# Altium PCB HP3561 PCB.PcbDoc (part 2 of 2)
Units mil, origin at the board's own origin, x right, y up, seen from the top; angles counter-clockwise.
Board outline 2229 x 3254 mil, 4 copper layers (Component Side, Signal Layer 2, Signal Layer 1, Solder Side), stack 33.234 mil thick; 84 components, 95 nets, 407 pads, 246 vias.
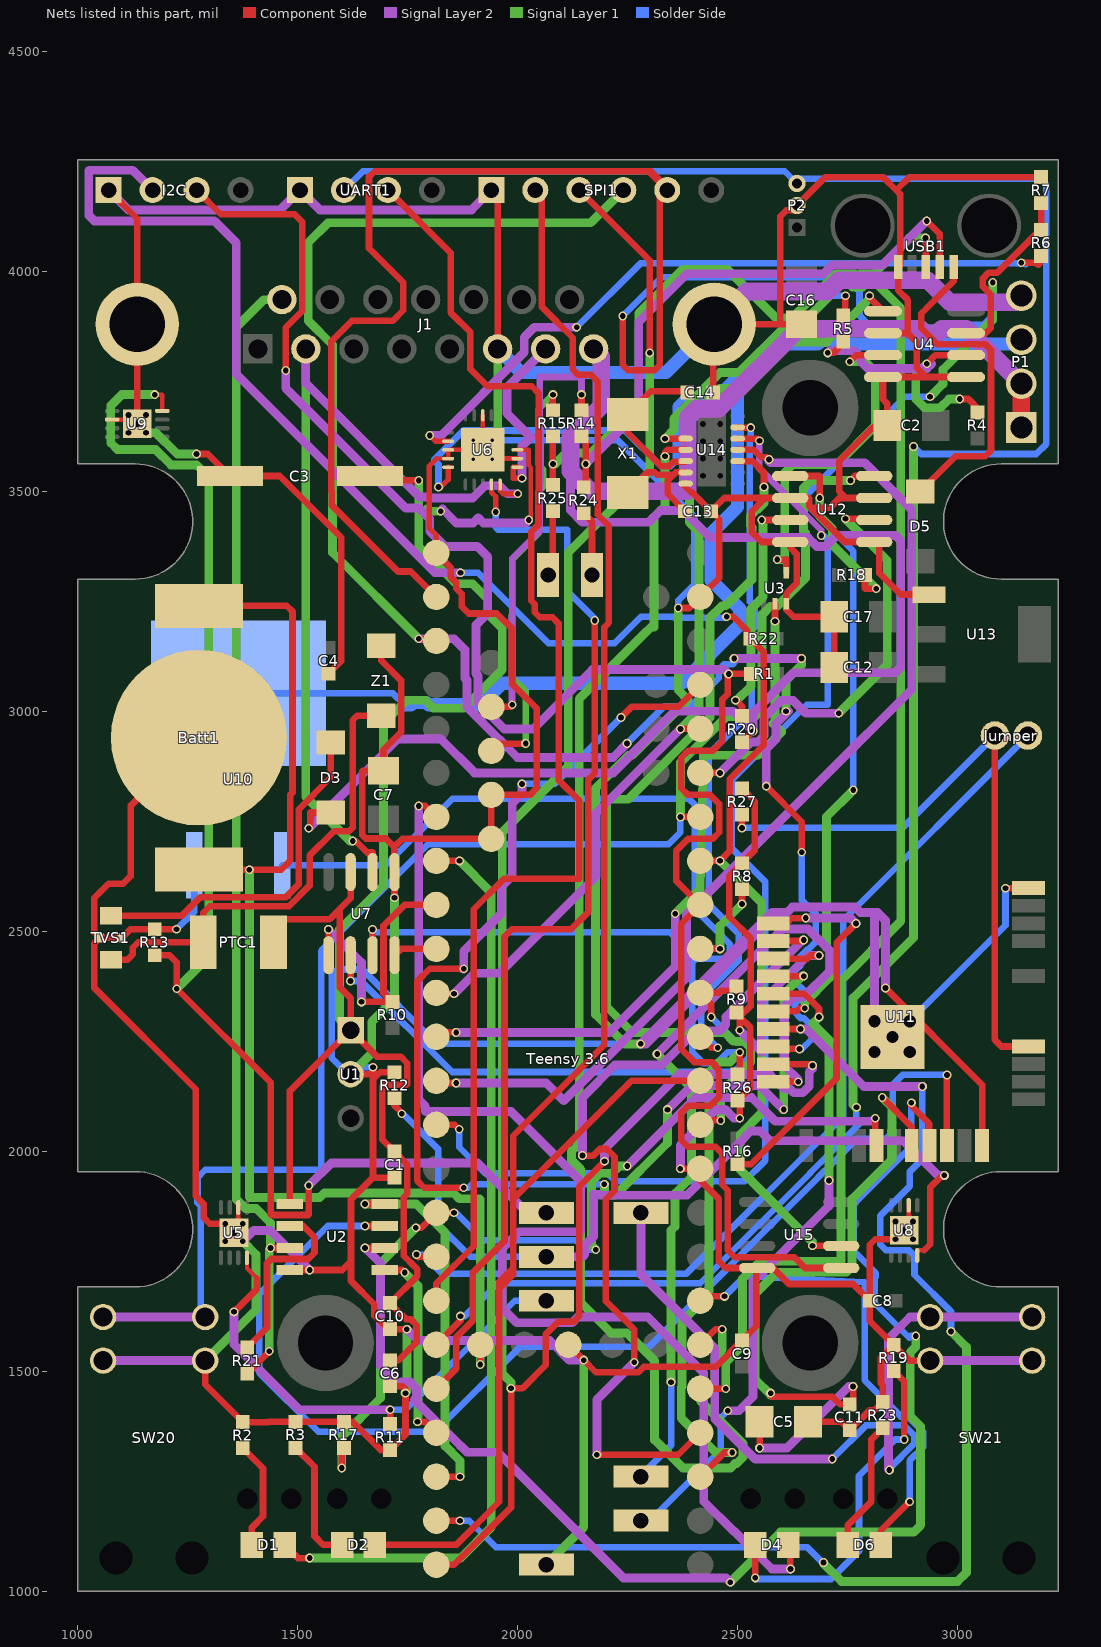
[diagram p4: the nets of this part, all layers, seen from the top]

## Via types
v1: diameter 20, hole 13, Component Side to Solder Side, 238 vias
v2: diameter 19.68, hole 7.87, Component Side to Solder Side, 4 vias
v3: diameter 50, hole 28, Component Side to Solder Side, 4 vias

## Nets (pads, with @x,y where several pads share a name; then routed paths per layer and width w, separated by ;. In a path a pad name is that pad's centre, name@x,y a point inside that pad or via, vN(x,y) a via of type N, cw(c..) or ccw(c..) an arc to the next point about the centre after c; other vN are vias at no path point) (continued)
GND: "Teensy 3.6.14" "Teensy 3.6.17" "Teensy 3.6.32" "Teensy 3.6.59" "Teensy 3.6.78" "Teensy 3.6.79" "Teensy 3.6.90" Batt1.2 C1.1 C2.1 C3.2 C4.2 C5.1 C6.1 C7.2 C8.1 C9.1 C10.2 C11.1 C12.1 C13.1 C14.1 C16.1 C17.1 I2C.1 J1.6 J1.16 J1.17 P1.4 P2.2 R2.2 R3.2 R7.2 R8.2 R9.2 R11.2 R12.2 R13.2 R17.2 R19.2 R23.2 R26.2 R27.1 SPI1.1 SW20.2 SW20.4 SW21.2 SW21.4 TVS1.3 U1.2 U2.8 U3.3 U4.2 U4.4 U4.5 U5.0 U5.2 U6.3 U6.4 U6.12 U6.18 U6.21 U7.5 U8.0 U8.2 U9.0 U9.2 U10.3 U11.9 U11.12 U11.28 U11.29 U12.2 U12.4 U12.5 U12.7 U13.1 U14.7 U15.4 UART1.1 USB1.4 Z1.1 | length 26968.1
  Component Side w10: U9.2@1077.91,3663.31 1115,3663.31 U9.0@1121.89,3663.31 ; U5.0@1364.84,1845.16 U5.2@1364.84,1872.09 ; 1816,3574.72 U6.4@1841.89,3574.72 U6.3@1841.89,3594.41 U6.21@1920.63,3594.41 U6.18@1920.63,3673.15 ; U8.0@2888.73,1850.16 U8.2@2888.73,1877.09
  Component Side w11.81: 1815,3360 1815,3400.44 1799.09,3416.34 1799.09,3557.82 1816,3574.72 ; U6.21@1944.25,3574.72 U6.12@1999.37,3574.72
  Component Side w14.76: U5.0@1364.84,1845.16 v1(1375,1835) ; U8.0@2888.73,1850.16 v1(2898.89,1840)
  Component Side w15: I2C.1@1070,4185 1135,4120 J1.16@1135,3880 U9.0@1135,3653.47 1144.53,3663 1155,3663 v1(1155,3673.47) ; v1(1115,3633.47) 1115,3663.31 v1(1115,3673.47) ; v1(1224.53,2504.53) R13.2@1175,2504.53 1119.53,2504.53 TVS1.3@1100,2485 TVS1.3@1050,2485 ; v1(1270,3585) 1295.55,3585 C3.2@1345.55,3535 1459,3535 1599,3395 1599,3114.47 C4.2@1570,3085.47 ; Batt1.2@1275,2940 1120,2785 1120,2625 1103,2608 1070,2608 1037,2575 1037,2498 TVS1.3@1050,2485 ; SW20.4@1289.5,1524 1289.5,1469.55 R2.2@1375,1384.05 1434,1384.05 1434.47,1384.53 R3.2@1495,1384.53 R17.2@1605,1384.53 1624.92,1384.53 1688.98,1320.47 R11.2@1710,1320.47 1745,1355.47 v1(1745,1450) 1745,1458.41 1737.94,1465.47 C6.1@1710,1465.47 ; v1(1335,1795) v1(1335,1835) 1300,1835 1286,1849 1286,1880 1268,1898 1268,2141 1037,2372 1037,2472 TVS1.3@1050,2485 ; U5.0@1355,1815 1365,1825 U5.0@1375,1825 ; v1(1375,1795) U5.0@1375,1825 ; v1(1375,1835) U5.0@1375,1825 ; U2.8@1482.13,1730 v1(1527,1730) 1601,1730 1621,1750 ; U1.2@1620,2175 1671,2175 ; v1(1671,2191) 1671,2175 ; Z1.1@1690,3149 1690,3115 1735,3070 1735,2952.5 1695,2912.5 C7.2@1695,2865.12 1648,2865.12 1647,2864.12 1647,2718.28 1654.39,2710.89 1700,2710.89 1720,2690.88 ; C10.2@1710,1595.47 1747.53,1595.47 v1(1748,1595) 1705,1595 1674,1626 1674,1652 1621,1705 1621,1750 ; C1.1@1720,1940 1671.75,1940 ; R12.2@1720,2179.53 1687.5,2179.53 1682.97,2175 ; v1(1720,2576) U7.5@1720,2634.49 1720,2690.88 ; 1815,3360 1847.5,3327.5 1847.5,3305.68 1860,3293.18 1860,3280 1872.56,3267.44 1872.56,3238.7 1888.76,3222.5 1952.5,3222.5 1987,3188 1987,3061.25 1988.75,3061.25 2043,3007 2043,2825 2028,2810 1940,2810 1940,2710 1737.5,2710 1720,2692.5 1720,2690.88 ; U6.21@1920.63,3594.41 1931.22,3605 1942.28,3605 v2(1942.28,3616.06) ; SPI1.1@1940,4185 1954.49,4170.51 J1.6@1954.49,3824.09 ; v2(1942.28,3572.76) U6.21@1944.25,3574.72 ; 2115,1560 v1(2150,1525) 2177.5,1497.5 2274.32,1497.5 2286.82,1510 2450.47,1510 C9.1@2510,1569.53 2542.5,1602.03 2542.5,1732.5 U15.4@2544.53,1734.53 ; v1(2365,3235) 2390,3235 2415,3260 2458,3303 2458,3436.53 C13.1@2439.53,3455 ; v1(2369.84,1960) 2415,1960 2415,1933.5 2457.5,1891 2457.5,1750 2472.97,1734.53 U15.4@2544.53,1734.53 ; U14.7@2381.89,3517.64 2381,3517.64 2381,3510.5 2393.5,3498 2396.53,3498 C13.1@2439.53,3455 ; C14.1@2444.53,3725 2444.53,3801 2446.81,3803.29 J1.17@2446.81,3880 2545,3880 2545.12,3879.88 2598,3879.88 ; v1(2505,2075) 2505,2110 R26.2@2500,2115 2529,2144 2529,2281.47 R9.2@2505,2305.47 ; v1(2505,2275) R9.2@2505,2305.47 ; R27.1@2510,2824.53 2539,2795.53 2539,2683.53 R8.2@2510,2654.53 2481,2625.53 2481,2533 2529.47,2484.53 2529.47,2329.94 R9.2@2505,2305.47 ; U11.12@2581.04,2437.79 2657.79,2437.79 2665,2445 v1(2685,2445) ; C16.1@2645,3879.88 2598,3879.88 ; C5.1@2660.12,1385 2735.47,1385 C11.1@2755,1365.47 2801,1411.47 2811.95,1411.47 R23.2@2830,1429.53 2830,1468 2826,1472 2826,1530.53 R19.2@2855,1559.53 ; C12.1@2719.88,3100 C17.1@2719.88,3215 2627.09,3215 2610.59,3231.5 U3.3@2610.59,3244.57 2610.59,3268 2634,3291.41 2634,3357.82 2619.53,3372.29 U12.4@2619.53,3385 2555,3385 2532.5,3407.5 2532.5,3455 2562.5,3485 ; U12.7@2810.47,3485 2746,3485 ; U4.2@2830.51,3860 2886,3860 ; v1(2836,2370.84) 3055.84,2151 U11.28@3055.84,2012.91 ; v1(2858.89,1800) 2812.97,1800 2800.47,1787.5 C8.1@2800.47,1660 ; v1(2898.89,1800) v1(2898.89,1840) ; U13.1@2934.84,3265.55 2871,3265.55 2822,3314.55 2822,3385 U12.5@2810.47,3385 2744,3385 2666.5,3462.5 ; SW21.2@2937.5,1524 2890.53,1524 R19.2@2855,1559.53 ; U4.5@3019.49,3760 2928.18,3760 ; v1(3109,2598) U11.9@3160.96,2598.03 ; R7.2@3190,4214.53 2890.53,4214.53 2860.5,4184.5 ; 1621,1750 1621,1890 1671,1940 ; 1671,1940 1671.75,1940 ; 1671,1940 1671,2175 ; 1671,2175 1682.97,2175 ; 1671.75,1940 1671.75,2163.78 1682.97,2175 ; C13.1@2439.53,3455 2469.53,3485 2562.5,3485 ; U15.4@2544.53,1734.53 2580.47,1734.53 2617,1698 2762.47,1698 C8.1@2800.47,1660 ; 2562.5,3485 U12.2@2619.53,3485 2662,3485 2663,3484 2663,3466 2666.5,3462.5 ; 2598,3879.88 2597,3880.88 2597,4125 2611,4139 2635,4139 P2.2@2635,4150 2699.53,4214.53 2830.47,4214.53 2860.5,4184.5 ; 2666.5,3462.5 2709,3462.5 2731.5,3485 2746,3485 ; 2746,3485 2731,3500 2731,3569 2808,3646 2839.88,3646 C2.1@2839.88,3650 2839.88,3700 2830.51,3709.37 U4.4@2830.51,3760 2928.18,3760 ; C8.1@2800.47,1660 2800.47,1614.05 R19.2@2855,1559.53 ; 2860.5,4184.5 2870,4175 2870,4015 USB1.4@2865,4010 2865,3957 2887,3935 2887,3861 2886,3860 ; 2886,3860 2907.5,3838.5 2907.5,3780.68 2928.18,3760
  Signal Layer 2 w20: SW20.2@1057.5,1524 SW20.4@1289.5,1524 ; I2C.1@1070,4185 1115,4140 1460,4140 UART1.1@1505,4185 1550,4140 1895,4140 SPI1.1@1940,4185 ; v1(1375,1795) 1400,1820 1437,1820 v1(1527,1730) ; v1(1748,1595) 1773.47,1569.53 2072.47,1569.53 2117,1525 v1(2150,1525) ; v2(1898.98,3572.76) v2(1942.28,3572.76) ; v2(1898.98,3616.06) v2(1942.28,3616.06) ; v1(2369.84,1960) 2369.84,2013.67 2451.17,2095 2471.88,2095 2491.88,2075 v1(2505,2075) ; v1(2505,2275) 2554.29,2225.71 2554.29,2339.29 2660,2445 v1(2685,2445) ; 2589,2543 2578.5,2543 v1(2279.5,2244) 2292,2244 2591,2543 2612.64,2543 2624.64,2555 2767.15,2555 2779.15,2543 2811,2543 ; v3(2811,2225.47) 2817.61,2225.47 U11.29@2851.91,2259.76 ; v3(2811,2295.47) 2811,2543 ; v1(2836,2370.84) 2836,2525 2818,2543 2811,2543 ; v1(2858.89,1800) v1(2898.89,1800) ; U8.0@2878.89,1820 2868.89,1830 2858.89,1830 v1(2858.89,1840) v1(2898.89,1840) ; SW21.2@2937.5,1524 SW21.4@3169.5,1524
  Signal Layer 2 w40: J1.17@2446.81,3880 2521.3,3954.49 2704.99,3954.49 2730.5,3980 2932,3980 2982,3930 3130,3930 P1.4@3145,3945
  Signal Layer 1 w20: v1(1155,3673.47) v1(1155,3633.47) 1177.53,3633.47 1226,3585 v1(1270,3585) ; SW20.4@1289.5,1524 1405,1639.5 1405,1765 v1(1375,1795) ; U1.2@1620,2175 1668,2223 1668,2294 1720,2346 v1(1720,2576) ; v1(1745,1450) 1743.5,1450 1748,1454.5 v1(1748,1595) ; v2(1942.28,3572.76) v2(1942.28,3616.06) 1954.49,3628.27 J1.6@1954.49,3824.09 ; 2065,1060 2150,1145 v1(2150,1525) ; v1(2279.5,2244) 2244,2244 2177,2311 2177,2825 2252,2900 2260.36,2900 2387,3026.64 2365,3048.64 v1(2365,3235) ; v3(2811,2225.47) v3(2811,2295.47) ; v3(2891,2225.47) v3(2891,2295.47)
  Solder Side w15: v1(1115,3633.47) v1(1155,3633.47) ; v1(1224.53,2504.53) 1265,2545 U10.3@1265,2649.84 ; v1(1335,1795) v1(1375,1795) ; v1(1671,2191) 1598.5,2191 1577,2212.5 1577,2400 1590,2413 1647,2413 1816,2244 v1(2279.5,2244) ; v2(1898.98,3616.06) v2(1942.28,3616.06) 2227.94,3616.06 2401,3443 2401,3288 2365,3252 v1(2365,3235) ; v3(2811,2225.47) v3(2891,2225.47) ; v3(2891,2295.47) 3109,2513.47 v1(3109,2598)
  Solder Side w30: J1.6@1954.49,3824.09 2008.58,3770 2336.81,3770 J1.17@2446.81,3880
"GPS RX": "Teensy 3.6.41" P2.3 UART1.2 | length 5337
  Component Side w15: 1815,1560 1870,1615 v1(1870,1625)
  Signal Layer 1 w20: v1(2770,2100) 2770,2097.84 2762.16,2105.67 2762.16,2348 2900,2485.84 v1(2900,3602)
  Solder Side w15: UART1.2@1605,4185 1648,4228 2607,4228 P2.3@2635,4200 2635,4211 3187.5,4211 3202,4196.5 3202,3608 3179,3585 2917,3585 v1(2900,3602) ; v1(1870,1625) 1880,1625 1955,1700 2415,1700 2665,1950 2665,1951.1 2689.9,1976 2691,1976 2780,2065 2770,2075 v1(2770,2100)
"GPS TX": "Teensy 3.6.40" UART1.3 | length 3029.2
  Component Side w15: UART1.3@1705,4185 1847.5,4042.5 1847.5,3907 1892,3862.5 1892,3778 1931,3739 2032,3739 2047.5,3723.5 2047.5,3424.5 2031,3408 2031,3251.28 2038.61,3243.68 2038.61,3225.39 2050,3214 2079,3214 2093,3200 2093,2844 2140,2797 2140,2620 2139,2619 1969,2619 1899.97,2549.97 1899.97,1783.97 1815,1699 1815,1660
"Hst USB_N": "Teensy 3.6.76" R14.1 | length 1000.3
  Component Side w15: 1940,3010 1954,2996 1968,3010 v1@1985,3010 ; R14.1@2145,3684.53 v1(2145,3720)
  Signal Layer 2 w15: v1(1987.5,3015) 1987.14,3015.36 1987.14,3216.89 1987.5,3217.24 1987.5,3347.5 2050,3410 2050,3518.18 2052.5,3520.68 2052.5,3632.79 2050,3635.29 2050,3760 2145,3760 v1(2145,3720)
"Hst USB_P": "Teensy 3.6.77" R15.1 | length 973.2
  Component Side w15: 1940,2910 1956.68,2926.68 v1(2018,2926.68) ; R15.1@2080,3684.53 v1(2080,3720)
  Signal Layer 1 w15: v1(2018,2926.68) 2018,3046 1987.5,3076.5 1987.5,3197.89 1987.14,3198.25 1987.14,3216.89 1987.5,3217.24 1987.5,3345 2047.5,3405 2047.5,3500.32 2057.5,3510.32 2057.5,3549.68 2047.5,3559.68 2047.5,3687.5 v1(2080,3720)
"J1708 RX": "Teensy 3.6.4" "Teensy 3.6.29" U4.1 | length 2243.6
  Component Side w15: 1815,2360 1817.21,2357.79 v1(1855,2357.79) ; v1(2370,2960) 2415,2960 ; v1(2800,3945) 2800,3940.51 U4.1@2830.51,3910
  Signal Layer 2 w20: v1(1855,2357.79) 1855.62,2357.79 1902.47,2404.64 1957.64,2404.64 2178,2625 2178,2768 v1(2370,2960)
  Signal Layer 1 w20: v1(2370,2960) 2412,3002 2412,3408.25 2390.25,3430 2390.25,3665.25 2459.65,3734.65 2506.3,3734.65 2611.65,3840 2702,3840 2800.51,3938.51 2800,3939.02 v1(2800,3945)
"J1708 TX": "Teensy 3.6.3" U3.2 | length 1614.3
  Component Side w15: 1815,2260 1825,2270 v1(1860,2270) ; v1(2585,3205) U3.2@2585,3244.57
  Signal Layer 2 w20: v1(1860,2270) 2208,2270 2358,2420 v1(2358,2540)
  Signal Layer 1 w20: v1(2358,2540) 2415,2597 2422,2900 2547,2900 2600,2953 2580.64,2972.36 2585,2976.72 v1(2585,3205)
J1708+: R5.2 U6.5 | length 1400.7
  Component Side w11.81: v1(1820,3510) 1825.47,3510 1825.97,3510.5 1841.89,3526.42 U6.5@1841.89,3555.04
  Component Side w15: R5.2@2740,3899.53 2745,3904.53 v1(2745,3945)
  Solder Side w15: v1(1820,3510) 1820,3561.41 1810,3571.41 1877,3638.41 2244.09,3638.41 2325,3557.5 2348,3557.5 2359,3568.5 2359,3694 2375,3710 2440,3710 2675,3945 v1(2745,3945)
J1708-: R6.2 U6.2 | length 1669
  Component Side w11.81: v1@1800,3624.91 v1(1800,3626.94) 1812.84,3614.09 U6.2@1841.89,3614.09
  Component Side w15: v1(3145,4020) 3178,4020 3183,4015 3190,4022 R6.2@3190,4035.47
  Signal Layer 2 w20: v1(1800,3626.94) 1825.59,3626.94 2015,3816.34 2015,3850.5 2037.5,3873 v1(2134,3873)
  Solder Side w15: v1(2134,3873) 2280,4019 v1@3152,4019 ; v1(3145,4020) 3151,4020 v1@3152,4019 ; v1@3152,4019 3158,4019 3155,4016 v1@3152,4019
LIN: J1.2 U6.10 U7.6 | length 2010.9
  Component Side w11.81: U6.10@1960,3515.67 1960,3501.5 1967.03,3494.47 v1(2000,3494.47)
  Component Side w15: v1(1625,2705) 1631.99,2705 1657.99,2679 1670,2679 U7.6@1670,2634.49
  Signal Layer 2 w20: J1.2@1518.27,3824.09 1518.27,3746.38 1777.64,3487 1797.64,3487 1799.64,3485 1898,3485 1925.68,3512.68 1958.32,3512.68 1976.53,3494.47 v1(2000,3494.47)
  Signal Layer 1 w20: J1.2@1518.27,3824.09 1518.27,2805.73 1619,2705 v1(1625,2705)
"LIN1 RX": "Teensy 3.6.6" R10.1 U7.1 | length 645
  Component Side w15: U7.1@1570,2445.51 v1(1570,2504) ; v1(1645,2339.53) R10.1@1715,2339.53 1695,2359.53 1695,2512.5 1742.5,2560 1815,2560
  Signal Layer 2 w20: v1(1570,2504) 1645,2429 v1(1645,2339.53)
"LIN1 TX": "Teensy 3.6.5" U7.4 | length 101
  Component Side w15: U7.4@1720,2445.51 1734.49,2460 1815,2460
"LIN !WAKE": "Teensy 3.6.24" R8.1 U7.3 | length 1112.9
  Component Side w15: U7.3@1670,2445.51 v1(1670,2504) ; v1(2510,2562) R8.1@2510,2595.47 ; 2415,2460 v1(2460,2460) 2415,2460
  Signal Layer 1 w20: v1(2460,2460) 2460,2512 v1(2510,2562)
  Solder Side w15: v1(1670,2504) 1676.5,2497.5 2347.68,2497.5 2385.18,2460 v1(2460,2460)
"LIN CS": "Teensy 3.6.23" R9.1 U7.2 | length 1359.2
  Component Side w15: v1(1620,2387) U7.2@1620,2445.51 ; v1(2440,2305) 2440,2335 2415,2360 2457,2360 2461.53,2364.53 R9.1@2505,2364.53
  Solder Side w15: v1(1620,2387) 1644,2387 1851,2180 2491.82,2180 2527.5,2215.68 2527.5,2234.32 2514.32,2247.5 2497.5,2247.5 v1(2440,2305)
"LIN Switch": "Teensy 3.6.42" U6.9 | length 2472.6
  Component Side w11.81: U6.9@1940.32,3515.67 1940.32,3497.41 1950,3487.73 v1(1950,3453)
  Component Side w15: 1815,1460 1860,1505 1860,1576.72 1897.5,1614.22 1897.5,1723 1970,1795.5 1970,2487.5 1987,2504.5 2121.5,2504.5 2160,2543 2160,2844 2175,2859 v1(2175,3206.53)
  Solder Side w15: v1(1950,3453) 1950,3418.28 1955.78,3412.5 2112.5,3412.5 2112.5,3273.82 2175,3211.32 v1(2175,3206.53)
NetBatt1_1: "Teensy 3.6.15" Batt1.1 | length 2703.2
  Component Side w15: Batt1.1@1275,2640 v1(1390,2640) 1462.5,2640 1482.5,2660 1482.5,2809.85 1488,2815.35 1488,3227 1475,3240 Batt1.1@1275,3240 ; v1(1915,1515) 1915,1560
  Signal Layer 1 w20: v1(1390,2640) 1390,1896 1391,1895 1550,1895 1560,1905 1854.12,1905 1867.12,1892 1913,1892 1915,1890 v1(1915,1515)
NetC5_2: C5.2 C11.2 U11.24 | length 1628.6
  Component Side w15: C5.2@2549.88,1385 2550,1384.88 v1(2550,1325.47) ; v1(2575,1450) 2575,1445 2578.5,1441.5 2716.03,1441.5 2733,1424.53 C11.2@2755,1424.53 2762.47,1432 v1(2762.47,1465) ; v1(2829,2122) 2895.84,2055.16 U11.24@2895.84,2012.91
  Signal Layer 2 w20: v1(2550,1325.47) 2612.97,1325.47 2752.5,1465 v1(2762.47,1465)
  Signal Layer 1 w20: v1(2575,1450) 2575,1446 2540,1481 2540,1675.5 2589.5,1725 2747.5,1725 2760,1737.5 2760,1891 2851,1982 2851,2100 v1(2829,2122)
NetC13_2: C13.2 U14.6 X1.1 | length 267.6
  Component Side w15: X1.1@2250,3497.83 2295.4,3543.23 2311.67,3543.23 2317.4,3537.5 2353.5,3537.5 2359.23,3543.23 ; C13.2@2380.47,3455 2341,3494.47 2341,3525 2359.23,3543.23 ; U14.6@2381.89,3543.23 2359.23,3543.23
NetC14_2: C14.2 U14.5 X1.2 | length 368
  Component Side w15: U14.5@2381.89,3568.82 2380.57,3567.5 2354.32,3567.5 2344.32,3557.5 2325.68,3557.5 2250,3633.18 X1.2@2250,3675 2302.5,3727.5 2382.97,3727.5 C14.2@2385.47,3725
NetD1_1: "Teensy 3.6.7" D1.1 | length 2108.8
  Component Side w15: D1.1@1470.4,1105 1500.4,1075 v1(1527,1075) ; 1815,2660 v1(1867.88,2660)
  Signal Layer 1 w20: v1(1527,1075) 1870,1075 1940,1145 1940,2587.88 v1(1867.88,2660)
NetD1_2: D1.2 R2.1 | length 249.6
  Component Side w15: R2.1@1375,1325 1421,1279 1421,1170 1395.6,1144.6 D1.2@1395.6,1105
NetD2_1: "Teensy 3.6.21" D2.1 SPI1.2 | length 4092.5
  Component Side w15: D2.1@1675.4,1105 1860,1105 1958,1203 1958,1687 ; SPI1.2@2040,4185 2055,4170 2055,3919.5 2125,3849.5 2125,3777.5 2137.5,3765 2167,3765 2182,3750 2182,3447 2207,3422 2207,3201 2197,3191 2197,2242 1990,2035 1990,1891 ; 2415,2160 2259,2160 1990,1891 ; 1958,1687 1958,1703 1990,1735 ; 1958,1687 1990,1719 1990,1735 ; 1990,1735 1990,1891
NetD2_2: D2.2 R3.1 | length 289.2
  Component Side w15: R3.1@1495,1325.47 1538,1282.47 1538,1125 1558,1105 D2.2@1600.6,1105
NetD3_2: D3.2 TVS1.1 | length 809.1
  Component Side w15: TVS1.1@1075,2535 1236,2535 1278,2577 1472,2577 1502.5,2607.5 1502.5,2777.5 1575,2850 D3.2@1575,2929
NetD4_1: "Teensy 3.6.8" D4.1 | length 2753
  Component Side w15: v1(1775,2785) 1790,2785 1815,2760 ; D4.1@2615.4,1105 2620,1100.4 v1(2620,1050)
  Signal Layer 2 w20: v1(1775,2785) 1775,2117.09 1790,2102.09 1790,2091 1791,2090 1985,2090 2143,1932 2143,1818 2142,1817 2003,1817 1965,1779 1965,1643 1998,1610 2123.71,1610 2136.71,1623 2295.71,1623 2423,1495.71 2423,1203.64 2489.83,1136.82 2491.18,1136.82 2578,1050 v1(2620,1050)
NetD4_2: D4.2 R19.1 | length 812.4
  Component Side w15: v1(2540.12,1030) 2540.12,1104.52 D4.2@2540.6,1105 ; R19.1@2855,1500.47 2878.89,1476.58 v1(2878.89,1344.47)
  Solder Side w15: v1(2540.12,1030) 2542.62,1027.5 2712.5,1027.5 2776,1091 2776,1262 2858.47,1344.47 v1(2878.89,1344.47)
NetD5_1: D5.1 USB1.1 | length 776.3
  Component Side w15: D5.1@2915,3500 2995,3580 3063,3580 3076,3593 3076,3821.5 3062.5,3835 2953.8,3835 2917.5,3871.3 2917.5,3904.32 2927.5,3914.32 2927.5,3914.5 2990.98,3977.98 USB1.1@2990.98,4010
NetD6_1: "Teensy 3.6.51" D6.1 | length 1098.2
  Component Side w15: 2415,1660 2425,1670 v1(2470,1670) ; D6.1@2825.4,1105 2825.4,1137.5 v1(2891,1203.1)
  Solder Side w15: v1(2470,1670) 2516,1716 2789,1702 2789,1479 2871.5,1396.5 2886.97,1396.5 2921.39,1362.08 2921.39,1326.87 2891,1296.48 v1(2891,1203.1)
NetD6_2: D6.2 R23.1 | length 298.4
  Component Side w15: D6.2@2750.6,1105 2750.6,1150 2804,1203.4 2804,1344.47 R23.1@2830,1370.47
NetI2C_2: "Teensy 3.6.26" I2C.2 R22.2 U15.6 | length 4073
  Component Side w15: 2415,2660 v1(2460,2660) 2481.75,2681.75 2481.75,2845.45 2559,2922.7 2559,3135.47 R22.2@2529.47,3165 2521.49,3172.99 2521.49,3183.99 2490.47,3215 v1(2475,3215) ; v1(2670,1785) 2735,1785 U15.6@2735.47,1784.53
  Signal Layer 2 w20: I2C.2@1170,4185 1125,4230 1026,4230 1025,4229 1025,4127.5 1037.5,4115 1310,4115 1360,4065 1360,3767 1812,3315 v1(1870,3315)
  Signal Layer 1 w20: v1(2460,2660) 2555,2565 2555,2087 2506,2038 2506,1957.53 2670,1793.53 v1(2670,1785)
  Solder Side w15: v1(1870,3315) 1910,3315 2070,3155 2220,3155 2280,3215 2353.18,3215 2355.68,3212.5 2472.5,3212.5 v1(2475,3215)
NetI2C_3: "Teensy 3.6.25" I2C.3 R1.2 U15.5 | length 4395.1
  Component Side w15: I2C.3@1270,4185 1325,4130 1492.5,4130 1510,4112.5 1510,3910 1472.5,3872.5 v1(1472.5,3775) ; R1.2@2530.47,3085 v1(2479.53,3085) 2477.5,3085 2477.5,3039.32 2465,3026.82 2465,2932 2443,2910 2387.5,2910 2372,2894.5 2372,2825 2387,2810 2437.5,2810 2458,2789.5 2458,2725 2443,2710 2387.5,2710 2360,2682.5 2360,2615 2415,2560 2372,2517 2372,2232.5 2402,2202.5 2442.5,2202.5 2448.5,2196.5 2448.5,2193.68 2457.5,2184.68 2457.5,2147 2458,2146.5 2458,2123.5 2437.5,2103 2387.5,2103 2372,2087.5 2372,2025 2387,2010 2450,2010 2465,1995 2465,1923.74 2477.5,1911.24 2477.5,1775 2493.5,1759 2629,1759 2653.47,1734.53 U15.5@2735.47,1734.53
  Signal Layer 2 w20: v1(1472.5,3775) 1472.5,3734.88 1745.38,3462 1776,3462 1800,3438 1800,3409.64 1834.64,3375 1908,3375 1931.94,3351.06 1931.94,3222.94 1905,3196 1905,3085.71 1910,3080.71 1910,3019.64 1970,2959.64 2034.64,2959.64 2170,3095 2469.53,3095 v1(2479.53,3085)
NetJumper_1: "Teensy 3.6.39" Jumper.1 | length 2226
  Component Side w15: v1(1770,1765) 1770,1763 1774,1759 1775,1760 1815,1760
  Solder Side w15: v1(1770,1765) 1785,1765 1829,1721 2382.82,1721 2740,2078.18 2740,2525 Jumper.1@3160,2945
NetJumper_2: Jumper.2 R27.2 U11.4 | length 1466.6
  Component Side w15: v1(2510,2735) R27.2@2510,2765.47 ; Jumper.2@3085,2945 3085,2253.03 3100,2238.03 U11.4@3160.96,2238.03
  Solder Side w15: v1(2510,2735) 2875,2735 Jumper.2@3085,2945
NetP1_3: P1.3 U10.2 | length 2513.4
  Solder Side w15: U10.2@1365,3041.57 1715.43,3041.57 1742,3015
  Solder Side w30: 1742,3015 1757.57,3015 1762.57,3020 1792.43,3020 1797.43,3015 1915.78,3015 1964.78,3064 2372.68,3064 2505,3196.32 2505,3233 2440,3298 2440,3405 2500,3465 2500,3594.17 2499.88,3594.29 2499.88,3635.71 2500,3635.83 2500,3724.36 2610.64,3835 2682.57,3835 2692.57,3845 2717.43,3845 2727.43,3835 3135,3835 P1.3@3145,3845
NetPTC1_1: PTC1.1 TVS1.2 Z1.2 | length 1075.9
  Component Side w15: TVS1.2@1075,2435 1112.5,2435 1125,2447.5 1125,2462.5 1137.5,2475 PTC1.1@1285,2475 1285,2542 1300,2557 1480.28,2557 1527,2603.72 1527,2672 1582.5,2727.5 1616.5,2727.5 1625,2736 1625,2980 1635,2990 Z1.2@1690,2990
NetR4_2: R4.2 R5.1 U4.6 | length 691.5
  Component Side w15: v1(2705,3815) 2718,3815 2740,3837 R5.1@2740,3840.47 ; v1(2930,3790) 2950,3810 U4.6@3019.49,3810 ; v1(3005,3710) 3024.53,3710 3050,3684.53 R4.2@3045,3679.53
  Signal Layer 2 w20: v1(2705,3815) 2710,3820 2765.36,3820 2780,3805.36 2780,3795.36 2796.07,3779.28 2930.46,3779.28 2941.18,3790 v1(2930,3790)
  Signal Layer 1 w20: v1(2930,3790) 2905,3765 2905,3710 2925,3690 2960.86,3690 2980.86,3710 v1(3005,3710)
NetR6_1: R6.1 R7.1 U4.7 | length 420
  Component Side w15: U4.7@3019.49,3860 3064,3860 3075.3,3871.3 3075.3,3947.89 3057.5,3965.68 3057.5,3984.32 3070.68,3997.5 3090.68,3997.5 3187.71,4094.53 R6.1@3190,4094.53 R7.1@3190,4155.47
NetR11_1: "Teensy 3.6.54" R11.1 U5.8 | length 1134.7
  Component Side w10: U5.8@1384.53,1757.91 1384.53,1734.11 1407.03,1711.61
  Component Side w15: v1(1355,1634.76) 1407.03,1686.79 1407.03,1711.61 ; R11.1@1710,1379.53 v1(1710,1412)
  Signal Layer 2 w20: v1(1355,1634.76) 1355,1561 1504,1412 v1(1710,1412)
  Solder Side w15: v1(1710,1412) 1745.18,1412 1993.18,1660 2065,1660
NetR12_1: "Teensy 3.6.53" R12.1 U8.8 | length 1961.4
  Component Side w10: U8.8@2908.42,1762.91 2908.42,1775 2924.5,1775
  Component Side w14.76: 2924.5,1775 2937,1787.5
  Component Side w15: R12.1@1720,2120.47 1720,2104 1736.38,2087.62 v1(1736.38,2085) ; 2937,1787.5 2937.5,1788 2937.5,1917.5 2965,1945 v1(2970,1945)
  Signal Layer 2 w20: 2065,1760 2147.5,1760 2152.5,1765 2152.5,1786.36 2172,1805.86 2172,1901.5 2185.14,1901.5 2186.64,1900 2385,1900 2515.6,2030.6 2515.6,2031.36 2530.24,2046 2550.95,2046 2573.43,2023.53 2876.47,2023.53 2955,1945 v1(2970,1945)
  Solder Side w15: v1(1736.38,2085) 1739,2085 1819,2005 1819,1833.5 1892.5,1760 2065,1760
NetR13_1: "Teensy 3.6.52" R13.1 U9.8 | length 3176.1
  Component Side w10: v1(1175,3720) 1191.7,3720 U9.8@1192.09,3682.99
  Component Side w15: R13.1@1175,2445.47 1208.53,2445.47 1225,2429 v1(1225,2369.5) 1439,2155.5 1439,1856 1440,1855 1524,1855 1525,1856 v1(1525,1922)
  Signal Layer 2 w20: v1(1525,1922) 1576,1973 1909,1973 2022,1860 2065,1860
  Signal Layer 1 w20: v1(1175,3720) 1100,3720 1075,3695 1075,3610 1075.36,3610 1090.36,3595 1176.96,3595 1211.96,3560 1270,3560 1297.66,3532.34 1297.66,2442.16 v1(1225,2369.5)
NetR14_2: R14.2 R24.2 USB1.2 | length 1366
  Component Side w15: R14.2@2145,3625.47 2155,3615.47 v1(2155,3562.5) 2155,3524.53 2145,3514.53 R24.2@2150,3509.53 ; v1(2930,4115) 2959.49,4085.51 USB1.2@2959.49,4010
  Signal Layer 2 w20: v1(2155,3562.5) 2275,3682.5 2275,3885 2385,3995 2696.01,3995 2716.01,4015 2830,4015 v1(2930,4115)
NetR15_2: R15.2 R25.2 USB1.3 | length 1465.6
  Component Side w15: R25.2@2080,3514.53 2075,3519.53 2080,3524.53 v1(2080,3562.5) 2080,3615.47 2075,3620.47 R15.2@2080,3625.47 ; v1(2926.99,4076) 2927.99,4077.01 USB1.3@2927.99,4010
  Signal Layer 1 w15: v1(2080,3562.5) v1@2085,3562.5
  Signal Layer 1 w20: v1@2085,3562.5 2110,3587.5 2167.5,3587.5 2275,3695 2275,3905 2375,4005 2476.65,4005 2586.65,3895 2624.29,3895 2724.29,3995 2765.71,3995 2770.71,3990 2774.29,3990 2779.29,3995 2810,3995 2891,4076 v1(2926.99,4076)
NetR16_1: R16.1 U11.10 | length 874.7
  Component Side w15: R16.1@2500,1970.47 2530.49,1970.47 2725,2164.98 2725,2473.79 v1(2769,2517.79) ; U11.10@2581.04,2517.79 2611.04,2517.79 2623.25,2530 v1(2655,2530)
  Signal Layer 2 w20: v1(2655,2530) 2756.79,2530 v1(2769,2517.79)
NetR17_1: "Teensy 3.6.38" R17.1 U11.22 | length 2095.2
  Component Side w15: v1(1600,1280) 1600,1320.47 R17.1@1605,1325.47 ; v1(1768.5,1826) 1781,1826 1815,1860 v1(1855,1860) ; v1(2812.97,2075) 2812.97,2035.85 2819.81,2029.02 U11.22@2815.84,2012.91
  Signal Layer 2 w20: v1(2249.18,1966.18) 2405,2122 2531.5,2122 2585.6,2067.9 2805.88,2067.9 v1(2812.97,2075)
  Signal Layer 1 w20: v1(1600,1280) 1600,1351 1688,1439 1688,1745.5 v1(1768.5,1826) ; v1(2177.5,1776) 2168,1785.5 2168,1931.36 2186.64,1950 2214.5,1950 2230.68,1966.18 v1(2249.18,1966.18)
  Solder Side w15: v1(1855,1860) 1860,1860 1922.5,1797.5 2132.68,1797.5 2154.18,1776 v1(2177.5,1776)
NetR18_2: R18.2 U12.1 | length 431.8
  Component Side w15: U12.1@2619.53,3535 2685.5,3535 2686.5,3534 v1(2686.5,3485) ; R18.2@2789.53,3310 2789.53,3279.47 2790,3279 v1(2815,3279)
  Signal Layer 1 w20: v1(2686.5,3485) 2686.5,3443.86 2715,3415.36 2715,3379 v1(2815,3279)
NetR20_2: R20.2 U12.3 | length 547
  Component Side w15: v1(2495,3025) 2496.75,3025 2510,3011.75 R20.2@2510,2989.05 ; v1(2555,3435) U12.3@2619.53,3435
  Signal Layer 1 w20: v1(2495,3025) 2498.25,3025 2530.64,3057.38 2530.64,3233.32 2558,3260.69 2558,3432 v1(2555,3435)
NetR21_1: R21.1 U2.6 | length 430
  Component Side w15: R21.1@1385,1553.53 1430,1598.53 1430,1745 1440,1755 1524,1755 1538,1769 1538,1804.5 1512.5,1830 U2.6@1482.13,1830
NetR26_1: "Teensy 3.6.62" R26.1 U10.1 | length 3000.7
  Component Side w15: 2415,1260 2470,1315 v1(2487.5,1315) ; R26.1@2500,2174.05 2505,2179.05 v1(2505,2225)
  Signal Layer 1 w20: v1(2487.5,1315) 2450,1315 2372,1393 2372,1462.93 2373.71,1464.64 2373.71,1612.71 2435,1674 2435,2180 2458.05,2203.05 2483.05,2203.05 v1(2505,2225)
  Solder Side w15: U10.1@1465,2649.84 1465,2650 1700,2650 1851,2801 2389.5,2801 2403,2787.5 2403,2550 2482.5,2470.5 2482.5,2450.68 2469.32,2437.5 2405.68,2437.5 2397,2428.82 2397,2225.5 2422.5,2200 2452.18,2200 2477.18,2225 v1(2505,2225)
NetSPI1_3: "Teensy 3.6.46" SPI1.3 U11.18 | length 4799.3
  Component Side w15: 1815,1060 1855,1060 1985,1190 v1(1985,1460.76) 2010.76,1460.76 2063.54,1513.54 2063.54,1583.54 2092,1612 2127,1612 2140,1625 2140,1919.53 v1(2197.47,1977) ; SPI1.3@2140,4185 2300,4025 v1(2300,3815) ; U11.18@2581.04,2197.79 2667.21,2197.79 v1(2670,2195)
  Signal Layer 2 w20: v1(2197.47,1977) 2197.47,2004.78 2367,2174.31 2573.73,2174.31 2606,2142.04 2618.19,2142.04 2627.44,2132.79 2648.15,2132.79 2662.79,2147.44 2662.79,2180.71 2670,2187.91 v1(2670,2195)
  Signal Layer 1 w20: v1(1985,1460.76) 1985,1474.29 1965,1494.29 1965,2725 2115,2875 2115,3361 2300,3546 v1(2300,3815)
NetSPI1_4: "Teensy 3.6.12" SPI1.4 U11.17 | length 4105
  Component Side w15: v1(1775,3165) 1820,3165 1815,3160 ; v1(2565,2830) 2645.94,2749.06 v1(2645.94,2679.47) ; U11.17@2581.04,2237.79 2586.33,2232.5 v1(2640.65,2232.5)
  Signal Layer 2 w20: v1(1775,3165) 1855,3165 1880,3140 1880,3075.36 1885,3070.36 1885,3009.29 1959.64,2934.64 1960,2934.64 1999.64,2895 2216.64,2895 v1(2248.32,2926.68) ; v1(2492,3120) v1(2645,3120) ; v1(2565,2830) 2565,2914.29 2587.32,2936.61 2587.32,2971.97 2615.36,3000 v1(2610,3000)
  Signal Layer 1 w20: v1(1775,3165) 1579,3361 1579,3833 1524,3888 1524,4066 1569,4111 2166,4111 SPI1.4@2240,4185 ; v1@2610,2999.85 v1(2610,3000) 2610,3069.73 2645,3104.73 v1(2645,3120)
  Solder Side w15: v1(2248.32,2926.68) 2331.64,3010 2391.81,3010 2457.03,3075.22 2457.03,3094.32 2470.21,3107.5 2489.31,3107.5 2492,3110.19 v1(2492,3120) ; v1(2640.65,2232.5) 2645.56,2232.5 2645.94,2232.12 2668.44,2254.62 2668.44,2284.32 2650.26,2302.5 2643.15,2302.5 2629.97,2315.68 2629.97,2334.32 2655.5,2359.85 2655.5,2360.71 2627.5,2388.71 2627.5,2407.35 2640.68,2420.53 2642.35,2420.53 2642.5,2420.68 2642.5,2442.68 2657.32,2457.5 2659.32,2457.5 2677.5,2475.68 2677.5,2539.32 2645.94,2570.88 v1(2645.94,2679.47)
NetSPI1_5: "Teensy 3.6.13" SPI1.5 U11.15 | length 5661.7
  Component Side w15: 1815,3260 1757,3318 1728,3318 1577,3469 1577,3500 1576,3501 1576,3841 1623,3888 1716.32,3888 1740,3911.68 1740,3974.64 1662,4052.64 1662,4215 1675,4228 2297,4228 ; v1(2239,3899) 2239,3787.5 2251.5,3775 2310.5,3775 2323,3787.5 SPI1.5@2323,4202 ; SPI1.5@2340,4185 SPI1.5@2323,4202 ; U11.15@2581.04,2317.79 2632.79,2317.79 2640,2325 v1(2652.47,2325) ; 2297,4228 SPI1.5@2323,4202 ; 2297,4228 2303,4228 2323,4208 SPI1.5@2323,4202
  Signal Layer 1 w20: v1(2652.47,2325) 2652.47,2337.47 2710,2395 2710,2455.36 2702,2463.36 2702,2760 v1(2763,2821) ; v1(2937.5,3715) 2967,3744.5 2967,3777 3080,3890 v1(3080,3975)
  Solder Side w15: v1(2239,3899) 2327,3987 2745,3987 2777,3955 2777,3900 2798,3879 2924.18,3879 2930.68,3872.5 2949.32,3872.5 2951.82,3875 2954.28,3875 2958.28,3879 3059,3879 3080,3900 v1(3080,3975) ; v1(2763,2821) 2762.5,2821.5 2762.5,3164.32 2763,3164.82 2763,3364.29 2656.52,3470.77 2656.52,3491.52 2880,3715 v1(2937.5,3715)
NetSW20_1: "Teensy 3.6.27" SW20.1 SW20.3 U12.8 | length 3436.5
  Component Side w15: v1(2370,2760) 2415,2760 ; v1(2756.5,3525) 2766.5,3535 U12.8@2810.47,3535
  Signal Layer 2 w20: SW20.1@1057.5,1623 SW20.3@1289.5,1623
  Signal Layer 1 w20: v1(2370,2760) 2370,2883.49 2474.51,2988 2539,2988 2555.64,3004.64 2555.64,3219.99 2574.64,3239 2590.32,3239 2654,3302.68 2654,3405.64 2650,3409.64 2650,3508.5 2666.5,3525 v1(2756.5,3525)
  Solder Side w15: SW20.3@1289.5,1623 1279,1633.5 1279,1876 1272,1883 1272,1940.5 1289.5,1958 1552,1958 1553,1959 1553,2455 1796,2698 2343,2698 2370,2725 v1(2370,2760)
NetSW21_1: "Teensy 3.6.68" SW21.1 SW21.3 | length 1818.9
  Signal Layer 2 w20: 2280,1860 2280,1720 2448,1552 2448,1392.12 2540.12,1300 v1(2715,1300) ; v1(2845,1275) 2843,1277 2843,1574 2892,1623 SW21.1@2937.5,1623 SW21.3@3169.5,1623
  Solder Side w15: v1(2715,1300) 2791.5,1376.5 2878.68,1376.5 2901.39,1353.79 2901.39,1335.15 2845,1278.76 v1(2845,1275)
"NetTeensy 3.6_1": "Teensy 3.6.1" U14.12 | length 2750.7
  Component Side w15: 1815,2060 1857,2060 v1(1867,2050) ; U14.12@2500,3620 2545,3620 2550,3615 v1(2549.88,3615)
  Signal Layer 2 w15: v1(2549.88,3615) 2548.82,3613.94 2548.82,3553 2690,3411.82 v1(2690,3400)
  Solder Side w15: v1(1867,2050) 1867,2009 1926,1950 2203.82,1950 2221.82,1932 2516,1932 2563.1,1979.1 2563.1,2611.9 2487,2688 2487,2845 2657,3015 2705,3015 2705,3390 2695,3400 v1(2690,3400)
"NetTeensy 3.6_2": "Teensy 3.6.2" U14.11 | length 2434.2
  Component Side w15: 1815,2160 1820,2155 v1(1860,2155) ; U14.11@2500,3594.41 2536.85,3594.41 2553.67,3577.58 2566.49,3577.58 v1(2571.32,3572.76)
  Signal Layer 2 w20: v1(1860,2155) 2064.69,2155 2104.69,2115 2383.59,2393.91 2383.59,2537.5 2796.09,2950 2796.36,2950 2896,3049.64 2896,3458.02 2789.02,3565 2575,3565 2571.32,3568.68 v1(2571.32,3572.76)
"NetTeensy 3.6_20": "Teensy 3.6.20" U14.10 | length 2081.9
  Component Side w15: 2415,2060 2416,2059 2427,2070 v1(2461.53,2070) ; U14.10@2500,3568.82 2534.15,3568.82 2560,3542.97 v1(2560,3510)
  Signal Layer 1 w20: v1(2461.53,2070) 2461.53,2133.53 2530,2202 2530,2235.36 2515.36,2250 2490,2250 2470,2270 2261,2270 2202,2329 2202,2799 2203,2800 2251.15,2800 2437,2985.85 2437,3212.36 2464.64,3240 2473,3240 2533,3300 2533,3418.04 2530,3421.04 2530,3445.36 2544.64,3460 2547,3460 2560,3473 v1(2560,3510)
"NetTeensy 3.6_22": "Teensy 3.6.22" U14.13 | length 1619.1
  Component Side w15: 2415,2260 2440,2235 v1(2455,2235) ; U14.13@2500,3645.59 2500.59,3645 v1(2530,3645)
  Solder Side w15: v1(2455,2235) 2417,2273 2417,2348 2502.5,2433.5 2502.5,2493.5 2434.03,2561.97 2434.03,2902.03 2532.5,3000.5 2532.5,3184.93 2538.5,3190.93 2538.5,3238.39 2527.5,3249.39 2527.5,3605.56 2527.38,3605.68 2527.38,3624.32 2530,3626.94 v1(2530,3645)
"NetTeensy 3.6_28": "Teensy 3.6.28" U12.6 | length 1013.1
  Component Side w15: 2415,2860 v1(2460,2860) ; v1(2745,3438) 2807.47,3438 U12.6@2810.47,3435
  Signal Layer 2 w20: v1(2460,2860) 2530,2930 2545.36,2930 2560,2944.64 2560,2985.36 2599.64,3025 2625.71,3025 2655,2995.71 v1(2729.79,2995.71)
  Signal Layer 1 w20: v1(2729.79,2995.71) 2840,3105.92 2840,3343 v1(2745,3438)
"NetTeensy 3.6_30": "Teensy 3.6.30" U11.13 | length 2988.5
  Component Side w15: v1(1877.47,1917) 1787.5,1917 1772,1932.5 1772,2387 1800,2415 v1(1877.47,2415) ; v1(2235,2986) 2259,3010 2365,3010 2415,3060 ; U11.13@2581.04,2397.79 2649.76,2397.79 v1(2650,2398.03)
  Signal Layer 2 w20: v1@1876.45,2413.98 v1(1877.47,2415) ; v1(2010,2835) 2010,2813.71 1987.5,2791.21 1987.5,2626.57 1962.5,2601.57 1962.5,2539.41 1877.47,2454.38 v1@1877.47,2419.62 ; v1(2340.5,2094.5) 2395.31,2149.31 2548.73,2149.31 2603.04,2095 v1(2605,2095) ; v1(1877.47,2415) 1872.86,2415 v1@1877.47,2419.62 ; v1(1877.47,2415) v1@1877.47,2419.62
  Signal Layer 1 w20: v1(2197,1925) 2197,1900 2222,1900 2340.5,2018.5 v1(2340.5,2094.5) ; v1(2605,2095) 2605,2357.29 2645.74,2398.03 v1(2650,2398.03)
  Solder Side w15: v1(1877.47,1917) 1888,1917 1896,1925 v1(2197,1925) ; v1(2010,2835) 2084,2835 v1(2235,2986)
"NetTeensy 3.6_45": "Teensy 3.6.45" U11.16 | length 2921.6
  Component Side w15: 1815,1160 v1(1868.76,1160) ; U11.16@2581.04,2277.79 v1(2643.15,2277.79)
  Signal Layer 2 w20: v1(2643.15,2277.79) 2655.71,2277.79 2786.5,2147 v1(2920,2147)
  Signal Layer 1 w20: v1(2695,1065) 2695,1063 2736,1022 3000,1022 3020,1042 3020,1555 v1(2985,1590)
  Solder Side w15: v1(1868.76,1160) 1890,1160 1950,1100 2658,1100 2693,1065 v1(2695,1065) ; v1(2920,2147) 2920,1982 2891,1953 2891,1920 2824.5,1853.5 2824.5,1787.5 2837,1775 2889.5,1775 2902,1762.5 2902,1719 2901.6,1719 2985,1635.6 v1(2985,1590)
"NetTeensy 3.6_49": "Teensy 3.6.49" U14.3 | length 3556.5
  Component Side w15: v1(2335,3620) U14.3@2381.89,3620 ; 2415,1460 v1(2473,1460)
  Signal Layer 1 w20: v1(2335,3620) 2355,3640 2355,3665.36 2460.15,3770.51 2503.51,3770.51 2603,3870 2634.65,3870 2734.65,3970 2755.36,3970 2760.36,3965 2784.64,3965 2789.64,3970 2818,3970 2871,3917 2871,2523 2735,2387 2735,1750 2551,1750 2511,1710 2511,1558 2473,1520 v1(2473,1460)
"NetTeensy 3.6_50": "Teensy 3.6.50" U14.4 | length 3142.5
  Component Side w15: v1(2335,3580) 2335,3588.7 2340.71,3594.41 U14.4@2381.89,3594.41 ; 2415,1560 2450,1595 v1(2465,1595)
  Signal Layer 1 w20: v1(2335,3580) 2335,3466.86 2310,3441.86 2310,3191 2306.5,3194.5 2295,3183 2294.64,3183 2140,3028.36 2140,2017.86 2122.5,2000.36 2122.5,1979.64 2143,1959.14 2143,1656 2212,1587 2248,1587 2311.3,1523.7 2311.3,1343.7 2375,1280 2484,1280 2494,1290 2497.86,1290 2512.5,1304.64 2512.5,1335 2415,1432.5 2448,1465.5 2448,1530.36 2465,1547.36 v1(2465,1595)
"NetTeensy 3.6_63": "Teensy 3.6.63" U11.11 | length 1952.8
  Component Side w15: v1(2147.5,1990) 2172,1990 2187,2005 2202.5,2005 2220,1987.5 2220,1910 2200,1890 2200,1659.5 2265,1594.5 v1(2265,1520) ; v1(2180,1310) 2365,1310 2415,1360 ; U11.11@2581.04,2477.79 2647.79,2477.79 v1(2650,2480)
  Signal Layer 2 w20: v1(2147.5,1990) 2147.5,2122.46 2221.04,2196 2327.36,2196 2405.36,2274 2459.5,2274 2473,2287.5 2473,2305 2648,2480 v1(2650,2480) ; v1(2180,1310) 2180,1435 v1(2265,1520)
"NetTeensy 3.6_72": "Teensy 3.6.72" U11.19 | length 1995.8
  Component Side w15: U11.19@2581.04,2157.79 v1(2637.79,2157.79)
  Signal Layer 2 w20: v1(2317,2221) 2601,2505 2660.36,2505 2710,2455.36 2710,2410.5 2649.5,2350 2626.56,2350 2606.44,2329.88 2606.44,2193.56 2637.79,2162.21 v1(2637.79,2157.79)
  Signal Layer 1 w20: v1(2317,2221) 2395,2143 2395,1941.29 2357.5,1903.79 2357.5,1828.79 2348.71,1820 v1(2348.71,1475)
  Solder Side w15: 2280,1260 2280,1262.4 2348.71,1331.12 v1(2348.71,1475)
"NetTeensy 3.6_74": "Teensy 3.6.74" U11.14 | length 1509.2
  Component Side w15: U11.14@2581.04,2357.79 2651.49,2357.79 2685,2324.29 v1(2685,2305)
  Signal Layer 2 w20: v1(2477.5,1410) 2503,1410 2535,1442 2535,1703 2707.5,1875.5 v1(2707.5,1933.5)
  Signal Layer 1 w20: v1(2685,2305) 2685,2304 2671,2290 2710,2251 2707.5,2248.5 v1(2707.5,1933.5)
  Solder Side w15: 2280,1160 2300.68,1160 2461.53,1320.85 2461.53,1394.03 v1(2477.5,1410)
NetU2_2: U2.2 U11.25 | length 3060.8
  Component Side w15: v1(1653,1780) U2.2@1697.87,1780 ; v1(2895,2110) 2895,2103.5 2935.84,2062.66 U11.25@2935.84,2012.91
  Signal Layer 2 w20: v1(1653,1780) 1688,1745 1688,1512 1729.82,1470.18 1734.64,1475 1755.36,1475 1770,1460.36 1770,1439.64 1765.18,1434.82 1870,1330 1870.36,1330 1885,1315.36 1954.64,1315.36 2240,1030 2473.5,1030 v1(2483.5,1020)
  Signal Layer 1 w20: v1(2483.5,1020) 2597.5,1134 2900,1134 2916,1150 2916,1374 2890,1400 2892.5,1402.5 2892.5,1542.64 2905,1555.14 v1(2905,1580)
  Solder Side w15: v1(2895,2110) 2895,2015 2897,2013 2764,1880 2764,1773 2814.41,1722.59 2814.41,1714.84 2811.7,1712.12 2811.7,1654.31 2890,1576 2894,1580 v1(2905,1580)
NetU2_3: U2.3 U11.26 | length 2707.1
  Component Side w15: v1(1653,1830) U2.3@1697.87,1830 ; U11.26@2975.84,2012.91 v1(2975.84,2173.47)
  Solder Side w15: v1(1653,1830) 1568,1830 1412,1674 1412,1497 1546.5,1362.5 1812.5,1362.5 2005,1555 2298.29,1555 2685,1941.71 2685,1942.82 2698.18,1956 2699.29,1956 2771.79,2028.5 2837.5,2028.5 2853,2044 2853,2151.47 2875,2173.47 v1(2975.84,2173.47)
NetU3_4: U3.4 U4.3 | length 791
  Component Side w15: v1(2590,3345) 2610,3345 2610.59,3345.59 U3.4@2610.59,3315.43 ; v1(2755,3795) 2770,3810 U4.3@2830.51,3810
  Signal Layer 1 w20: v1(2590,3345) 2605,3345 2607,3343 2607,3543.04 2625,3561.04 2725.04,3561.04 2812.97,3648.97 2812.97,3772.03 2790,3795 v1(2755,3795)
RAW: D3.1 J1.8 P1.1 P1.2 R20.1 | length 4709.9
  Component Side w15: v1(1525,2734) 1527.99,2736.99 1529,2770 D3.1@1575,2770 ; R20.1@2510,2930 v1(2535,2955)
  Component Side w40: P1.1@3145,3645 P1.2@3145,3745
  Signal Layer 2 w20: v1(1525,2734) 1728,2937 1825,2937 1902,2860 2217,2860 2357,3000 2490,3000 v1(2535,2955) 2535,2995.71 2626.79,3087.5 2858.5,3087.5 2871,3100 2871,3387.5 2858.5,3400 2725.36,3400 2700.36,3375 2679.64,3375 2659.64,3395 2438.24,3395 2376.74,3456.5 2324.64,3456.5 2298.14,3430 2147,3430 2120,3457 2120,3545.5 ; J1.8@2172.6,3824.09 J1.8@2190,3806.69
  Signal Layer 2 w40: J1.8@2190,3806.69 2190,3694 2120,3624 2120,3545.5 2165.5,3500 2386.26,3500 2386.26,3667.96 2406.76,3688.47 2457.12,3688.47 2638.66,3870 2915.5,3870 2925.5,3860 2954.5,3860 2964.5,3870 3020,3870 P1.2@3145,3745
"Safe 12V": C1.2 C3.1 C6.2 C10.1 PTC1.2 U1.1 U2.5 U6.13 U7.7 | length 4271.1
  Component Side w10: U6.13@1999.37,3594.41 2025,3594.41 2025,3559.25 2030,3554.25 2030,3440 v1(2025,3435)
  Component Side w15: PTC1.2@1445,2475 1445,2527 1572,2527 1595,2550 ; U2.5@1482.13,1880 1482,1880 1482,2137 U1.1@1620,2275 ; U7.7@1620,2634.49 1620,2575 1595,2550 ; C3.1@1664.45,3535 1674.45,3525 v1(1775,3525) ; C6.2@1710,1524.53 1728.73,1524.53 1770.5,1566.3 1770.5,1604.32 1757.32,1617.5 1747.03,1617.5 C10.1@1710,1654.53 1772,1716.53 1772,1731.5 1767,1736.5 1766.68,1736.5 1741,1762.18 1741,1895 1749,1903 1749,1970.05 C1.2@1720,1999.05 1691.75,2027.3 1691.75,2148 1694.75,2151 1748,2151 1749,2152 1749,2200 1734,2215 1680,2215 U1.1@1620,2275 ; 1595,2550 1595,2373 1620,2348 U1.1@1620,2275
  Signal Layer 2 w20: v1(1825,3455) 1825,3456 1829,3460 1861,3428 1898.36,3428 1910.36,3440 1922.36,3428 2018,3428 v1(2025,3435)
  Signal Layer 1 w20: U1.1@1620,2275 1595,2300 1595,2504 1695,2604 1695,2972.5 1747.5,3025 1790.36,3025 1808.31,3007.04 1877.4,3007.04 1965,3094.64 1965,3188.57 1931.94,3221.63 1931.94,3255.36 1897.3,3290 1859.64,3290 1775,3374.64 v1(1775,3525) ; 1778,3445 1793,3460 1798,3455 v1(1825,3455)
SHLD/LIN: J1.7 U6.11 | length 418.3
  Component Side w11.81: U6.11@1999.37,3555.04 1990,3555.04 1990,3530 1992.88,3532.88 1995.76,3530 v1(2010,3530)
  Signal Layer 2 w20: v1(2010,3530) 2010,3603.47 2030,3623.47 1975.37,3678.1 1975.37,3735.92 J1.7@2063.54,3824.09
SWCAN: J1.9 R21.2 U2.7 | length 2621.1
  Component Side w15: R21.2@1385,1494.47 1435,1544.47 v1(1435,1545) ; v1(1438,1780) U2.7@1482.13,1780
  Signal Layer 1 w20: v1(1435,1545) 1435,1777 v1(1438,1780) 1438,1837 1405,1870 1380.5,1870 1360,1890.5 1360,3873 1422.91,3935.91 J1.9@1463.74,3935.91
SWCANRX: "Teensy 3.6.44" U2.4 | length 876.1
  Component Side w15: v1(1653,1880) U2.4@1697.87,1880 ; 1815,1260 v1(1868.76,1260)
  Signal Layer 1 w20: v1(1653,1880) 1769.22,1880 1835,1814.22 1835,1330 1868.76,1296.24 v1(1868.76,1260)
SWCANTX: "Teensy 3.6.43" U2.1 | length 452.8
  Component Side w15: U2.1@1697.87,1730 1737,1730 v1(1743,1724) ; v1(1772,1385) 1790,1385 1815,1360
  Signal Layer 1 w20: v1(1743,1724) 1773,1694 1773,1386 v1(1772,1385)
"USB D_N": "Teensy 3.6.82" R24.1 | length 148.3
  Component Side w15: R24.1@2150,3450.47 2169,3431.47 2169,3310
"USB D_P": "Teensy 3.6.83" R25.1 | length 150
  Component Side w15: 2069,3310 2080,3321 R25.1@2080,3455.47
pads on no net: "Teensy 3.6.16" "Teensy 3.6.18" "Teensy 3.6.19" "Teensy 3.6.31" "Teensy 3.6.35" "Teensy 3.6.36" "Teensy 3.6.37" "Teensy 3.6.61" "Teensy 3.6.88" "Teensy 3.6.91" L1. L2. L3. L4. SW20. SW21. U3.1 U6.14 U6.15 U6.16 U6.17 U7.8 U11.1 U11.2 U11.3 U11.5 U11.6 U11.7 U11.8 U11.21 U11.27 U14. U14.8 U14.9 U15.1 U15.2 U15.3 U15.7 USB1.0 USB1.5

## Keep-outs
Keep-Out Layer:
  the board outline again, w10

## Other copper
Component Side:
  rectangle net 3V3: 3010,2989.05 3225,3300
Solder Side:
  rectangle net 3V3: 2800,3295 2960,3565
  rectangle net 3V3: 2836,2990 3225,3300.5
  rectangle: 2410,3500.68 2473,3685
  rectangle net NetP1_3: 1135,1980 1535,2265
  rectangle net NetP1_3: 1015,1980 1185,2765
  rectangle net NetP1_3: 1295,3170 1760,3730
  rectangle net NetP1_3: 1010,2750 1760,3290

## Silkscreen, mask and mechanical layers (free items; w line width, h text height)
Mechanical 1:
  text "Dots are anodes" at 1304.25,850 h40

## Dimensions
2665,1564 to 3229,1000 on Mechanical 1
1000,1000 to 3229,1000 on Mechanical 1
1000,1000 to 1000,4254 on Mechanical 1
